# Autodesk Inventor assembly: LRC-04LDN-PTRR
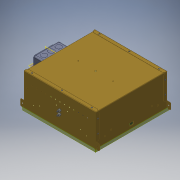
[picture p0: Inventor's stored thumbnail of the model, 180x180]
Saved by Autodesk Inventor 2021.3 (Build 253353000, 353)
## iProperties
Part Number: LRC-04LDN-PTRR
Document SubType Name: Assembly
Designer: JChurch
Author: JChurch
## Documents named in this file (5)
- X:\Revit Files\0000-Un-Zipped\COB\LRC-04LDN-PTR\LRC-04LDN-PTRR.iam
- X:\INVENTOR\830\830520-00-00.ipt
- X:\INVENTOR\881\881088-00-00.iam
- X:\INVENTOR\750\750472-00-00.iam
- X:\INVENTOR\725\725383-01-00.ipt
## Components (4 placed, 4 different names)
1. 830520-00-00:1 — Mate:1, Mate:2, Mate:3, Mate:4, Tangent:1, Angle:1, Insert:2
2. 881088-00-00:1 [sub-assembly] — Mate:4, Tangent:1, Angle:1
3. 750472-00-00:1 [sub-assembly] — Insert:1, Insert:2
4. 725383-01-00:1 — Insert:1
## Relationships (8: Mate 4, Insert 2, Tangent 1, Angle 1)
- Mate:1: 830520-00-00:1
- Mate:2: 830520-00-00:1
- Mate:3: 830520-00-00:1
- Mate:4: 830520-00-00:1 ↔ 881088-00-00:1
- Tangent:1: 830520-00-00:1 ↔ 881088-00-00:1
- Angle:1: 830520-00-00:1 ↔ 881088-00-00:1
- Insert:1: 750472-00-00:1 ↔ 725383-01-00:1
- Insert:2: 830520-00-00:1 ↔ 750472-00-00:1
